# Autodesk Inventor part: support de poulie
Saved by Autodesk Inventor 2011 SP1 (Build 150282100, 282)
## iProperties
Created: 2010-12
Part Number: support de poulie
Document SubType Name: Modeling
Designer: eric
Density: 1 g/cm^3
Author: eric
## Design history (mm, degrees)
feature "Base1"
node "Solide1"
node "Corps solides"
node "Corps surfaciques"
